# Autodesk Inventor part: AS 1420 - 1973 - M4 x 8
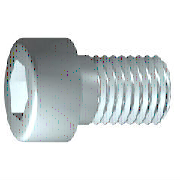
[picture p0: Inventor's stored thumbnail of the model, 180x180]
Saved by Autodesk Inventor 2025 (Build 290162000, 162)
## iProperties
Created: 2024-01
Part Number: AS 1420 - 1973 - M4 x 8
Material: Acciaio, Dolce
Description: Viti con esagono incassato metriche ISO
Document SubType Name: Modeling
Standard: AS 1420 - 1973
Designer: 18907419
Standards Organization: AS
Language: it-IT
Size Designation: M4 x 8
Categories: <MemberInstance><Categories><Category DisplayName="Elementi di fissaggio" InternalName="e4da775c-781d-43d5-af7c-5136215cf5a6" Mnemonic="FSTN"><Category DisplayN
Density: 7.85 g/cm^3
Appearance: Semilucidato
IsCustomPart: 0
Author: 18907419
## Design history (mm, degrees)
body "Solid1"
workplane "Work Plane1"
fillet "Fillet2" dims "d30" = 0.1 (= R)
revolve "Corpo" stored, may be unused: angle "d10" = 90 deg
sketch "Schizzo2"
  geometry: L1 (0, -4.9)-(0, 4.9) reference; L2 (-4.9, 0)-(4.9, 0) reference; L3 (1.732, 0)-(0.866, -1.5); L4 (0.866, -1.5)-(-0.866, -1.5); L5 (-0.866, -1.5)-(-1.732, 0); L6 (-1.732, 0)-(-0.866, 1.5); L7 (-0.866, 1.5)-(0.866, 1.5); L8 (0.866, 1.5)-(1.732, 0); 2 further points
  constraints: 12 end point, 1 coincident, 1 horizontal alignment, 1 point on line, 12 other
extrude "Intaglio" join sketch "Schizzo2" stored distance "d11" = 10; taper "d12" = 0 deg
fillet "Raccordo1" dims "d17" = 0.4 (= RR)
feature "Filettatura" dims "d13" = 6.25 (= GEL), "d14" = 0
chamfer "Smusso1" distance "d15" = 0.42941 (= -0.5 x SPD + 0.5 x GD); stored, may be unused: second distance "d16" = 0.42941 (= GUL), angle "d27" = 45 deg
sketch "Schizzo1"
  geometry: L1 (-1, 0)-(8, 0); L2 (8, 0)-(8, 2); L3 (8, 2)-(1.75, 2); L4 (1.75, 2)-(1.32, 2); L5 (1.32, 2)-(0, 2); L6 (0, 2)-(0, 3.5); L7 (0, 3.5)-(-4, 3.5); L8 (-4, 3.5)-(-4, 1.732); L9 (-4, 1.732)-(-2, 1.732); L10 (-2, 1.732)-(-1, 0); L11 (-6.4, 0)-(10.4, 0) reference; L12 (0, -0.7)-(0, 4.2) reference; L13 (1.75, 2)-(0, 2)
  constraints: 22 end point, 6 parallel, 2 collinear, 2 perpendicular, 1 horizontal, 1 point on line
  dimensions: "d1" = 6.25 distance from line of L3.end L2 (= GEL); "d2" = 0.42952 distance of L4.end L3.end (computed from GAL); "d3" = 4 distance between parallel lines of L8 L6 (= KOH); "d4" = 2 distance of L8.end L9.end (= INTI); "d5" = 60 deg angle of L10 L1; "d6" = 4 diameter of L3 L1 (= GD); "d7" = 4 diameter of L5 L1 (= BDM); "d8" = 3.4641 diameter of L9 L1 (= 1.1547 x SW); "d9" = 7 diameter of L7 L1 (= KOD); "d26" = 8 distance between parallel lines of L12 L2 (= NLG)
other parameters: "GD" = 4 (= NND) [user parameter; used in 2 equation terms], "NLG" = 8 [user parameter; used in 1 equation term], "GEL" = 6.25 [user parameter; used in 2 equation terms], "KOD" = 7 [user parameter; used in 1 equation term], "KOH" = 4 (= NND) [user parameter; used in 1 equation term], "INTI" = 2 [user parameter; used in 1 equation term], "GAL" = 0.42941 (= 0.61345 x PTC) [user parameter; used in 1 equation term], "GUL" = 0.42941 (= 0.61345 x PTC) [user parameter; used in 1 equation term], "BDM" = 4 (= NND) [user parameter; used in 1 equation term], "SW" = 3 [user parameter; used in 2 equation terms], "RR" = 0.4 (= 0.1 x NND) [user parameter; used in 1 equation term], "SPD" = 3.14117 (= NND - 1.2269 x PTC) [user parameter; used in 1 equation term], "d19" = 0, "d28" = 0, "d29" = 0, "R" = 0.1 [user parameter; used in 1 equation term], "PHH" = 0.13 [user parameter], "GD1" = 3.14117 (= THREADDIA - 1.2269 x PTC) [user parameter], "THREADDIA" = 4 [user parameter; used in 1 equation term], "FAWI" = 45 deg [user parameter], "TPU" = 14.28571 (computed from PTC) [user parameter], "PTC" = 0.7 [user parameter; used in 5 equation terms], "KOH1" = 3.6 [user parameter], "NND" = 4 [user parameter; used in 5 equation terms], "TOA" = 30 deg [user parameter], "E0" = 3.465 (= 1.155 x SW) [user parameter]
